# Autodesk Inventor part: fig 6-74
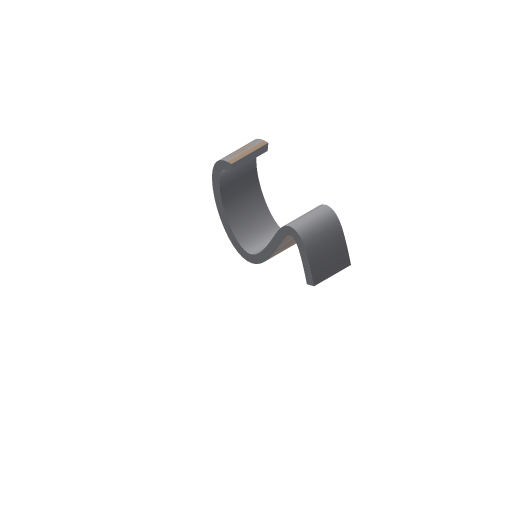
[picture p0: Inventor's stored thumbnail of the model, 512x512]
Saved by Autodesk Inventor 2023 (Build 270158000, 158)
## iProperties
Part Number: fig 6-74
Document SubType Name: Modeling
Created: 2002-12
Designer: deepak
Density: 1 g/cm^3
Material: Generic
Appearance: Default
Control State: 0
Master: False
Checked Out: False
Shininess: 64.0
Length Units: 11269
Angle Units: 11279
Time Units: 11290
Mass Units: 11283
Length Display Precision: 3
Angle Display Precision: 2
Compacted: True
Density: 0.0
Volumn: 0.0
Area: 0.0
PropertySet Name: Model Information
Author: deepak
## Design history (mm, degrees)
sketch "Sketch1"
  geometry: 5 further points
  constraints: 5 other
extrude_surface "ExtrusionSrf1" sketch "Sketch1" dims "d0" = 20, "d1" = 0
thicken "Thicken2" dims "d6" = 4, "d7" = 4
body "Solid1"
body "Srf1"
